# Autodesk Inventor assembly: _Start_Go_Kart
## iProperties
Shininess: 50.0
Angle Display Precision: 2
Document Length Units: 11269
Document Angle Units: 11279
Document Time Units: 11290
Document Mass Units: 11283
Document Length Units Precision: 3
Document Angle Units Precision: 2
Compacted: True
Created: 2001-08
Part Number: _Start_Go_Kart
Document SubType Name: Assembly
Designer: Martin Budgell
Density: 0.0
Volumn: 0.0
Area: 0.0
PropertySet Name: Model Information
Control State: 0
Master: False
Checked Out: False
Author: Martin Budgell
